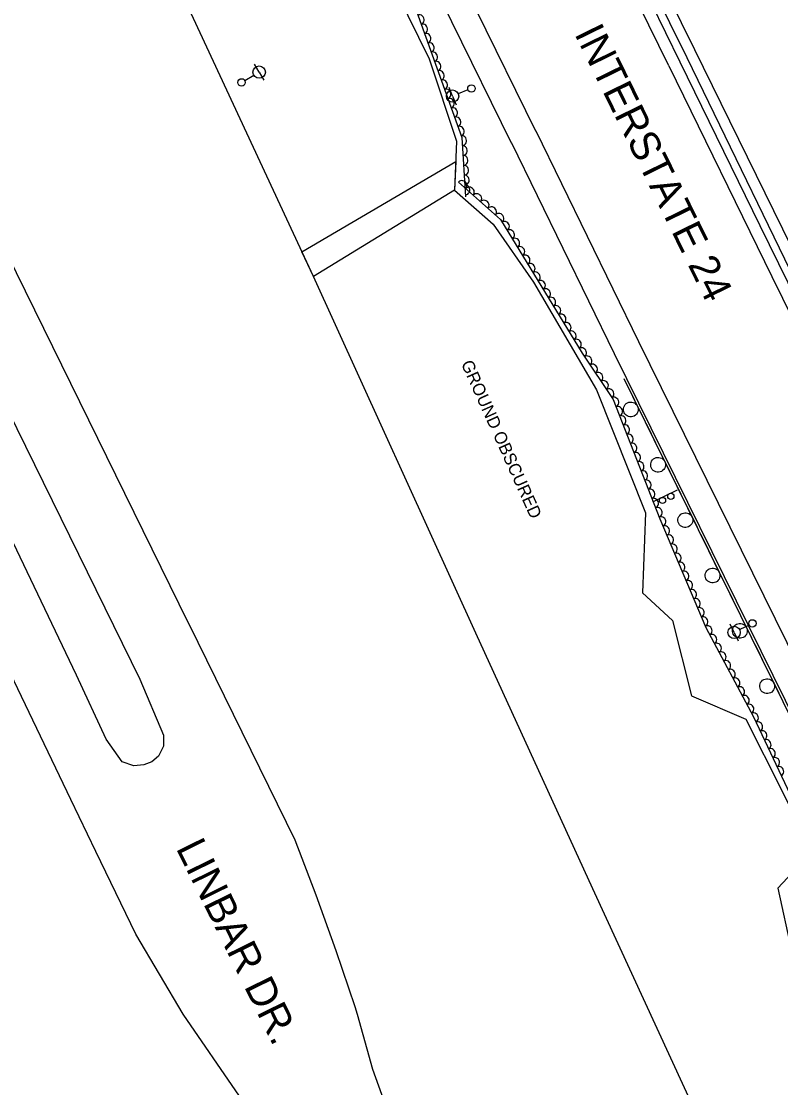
# Model space of a CAD drawing. Extents: x 1746719 to 1766531, y 631721 to 662391.
# Drawn here: x 1762510.8 to 1762818.3, y 636284.6 to 636716.8 of the extents above; entities that cross this region are included whole.
import ezdxf

# ---------------------------------------------------------------- set-up
doc = ezdxf.new("R2010")
doc.units = 0
for name, color, linetype in [('SURVEY - AERIAL SURVEY - Photo Control - Points - Elevations', 7, 'Continuous'), ('SURVEY - AERIAL SURVEY - Photo Control - Points - Locators', 7, 'Continuous'), ('SURVEY - AERIAL SURVEY - Photo Control - Points - Numbers', 7, 'Continuous'), ('SURVEY - AERIAL SURVEY - Photo Control with Text', 7, 'Continuous'), ('SURVEY - CENTERLINE - Existing Roads - Development', 7, 'Continuous'), ('SURVEY - CONTROL - Grid', 7, 'Continuous'), ('SURVEY - CONTROL - Points - Numbers', 7, 'Continuous')]:
    doc.layers.add(name, color=color, linetype=linetype)

msp = doc.modelspace()

# ---------------------------------------------------------------- linework, layer by layer
at = {"layer": 'SURVEY - AERIAL SURVEY - Photo Control - Points - Elevations'}
for points in [[(1762773.06, 636698.72), (1762724.62, 636797.23), (1762665.78, 636917.21), (1762608.96, 637033.7), (1762547.76, 637159.19), (1762483.24, 637291.54), (1762429.61, 637401.09), (1762367.13, 637528.71), (1762311.22, 637643.03), (1762248.83, 637770.86), (1762183.89, 637904.12), (1762125.15, 638021.3), (1762090.32, 638088.89)], [(1762783.5, 636705.24), (1762745.76, 636781.92), (1762702.74, 636870.15), (1762649.08, 636980.15), (1762603.69, 637072.36), (1762560.73, 637160.61), (1762512.91, 637258.85), (1762467.62, 637351.57), (1762419.77, 637449.66), (1762380.4, 637529.73), (1762340.69, 637610.68), (1762307.07, 637679.74), (1762272.3, 637751.43), (1762238.92, 637822.21), (1762204.21, 637890.89), (1762159.32, 637981.97)], [(1762719.21, 636672.25), (1762670.76, 636770.78), (1762611.89, 636890.84), (1762555.03, 637007.4), (1762493.83, 637132.9), (1762429.32, 637265.2), (1762375.72, 637374.71), (1762313.23, 637502.34), (1762254.75, 637621.92)], [(1762709.34, 636667.39), (1762660.89, 636765.94), (1762602, 636886.01), (1762545.14, 637002.58), (1762483.94, 637128.07), (1762419.44, 637260.37), (1762365.84, 637369.88), (1762303.35, 637497.51), (1762244.87, 637617.09)], [(1762369.56, 636898.24), (1762574.58, 636480.72), (1762582.23, 636465.15), (1762621.56, 636385.05), (1762630.03, 636362.79), (1762638.1, 636340.23), (1762645.78, 636317.47), (1762646.76, 636314.45), (1762653.05, 636292.18), (1762660.8, 636270.32)], [(1762557.07, 636346.83), (1762540.94, 636380.33), (1762530.76, 636401.45), (1762325.19, 636830.85)], [(1763641.05, 634952.58), (1763576.52, 635085.11), (1763508.91, 635223.28), (1763437.7, 635368.38), (1763363.42, 635520.08), (1763276.58, 635697.4), (1763200.09, 635854.25), (1763123.66, 636010.44), (1763058.89, 636142.6), (1762979.2, 636306.01), (1762911.72, 636443.92), (1762783.5, 636705.24)], [(1762556.36, 636415.05), (1762551.56, 636416.65), (1762545.17, 636425.84), (1762533.17, 636451.84), (1762423.17, 636681.84), (1762421.56, 636690.24), (1762421.56, 636695.05), (1762423.56, 636697.84), (1762428.76, 636700.24), (1762433.56, 636700.24), (1762438.76, 636694.65), (1762476.76, 636617.05), (1762558.76, 636450.24), (1762568.36, 636427.45), (1762568.36, 636423.05), (1762566.36, 636419.05), (1762563.56, 636416.65), (1762560.36, 636415.45), (1762556.36, 636415.05)], [(1762773.06, 636698.72), (1762814.67, 636613.42), (1762883.84, 636472.89), (1762954.11, 636329.07), (1763023.11, 636188.11), (1763074.26, 636083.06), (1763161.07, 635905.77), (1763211.77, 635802.95), (1763267.45, 635689.5), (1763370.88, 635477.29), (1763451.14, 635313.44)], [(1762719.13, 636672.41), (1762760.79, 636587.02), (1762829.97, 636446.47), (1762900.21, 636302.71), (1762969.19, 636161.79), (1763020.34, 636056.74), (1763107.22, 635879.31), (1763157.93, 635776.46), (1763213.56, 635663.14), (1763316.97, 635450.95), (1763397.25, 635287.05)], [(1762709.25, 636667.59), (1762750.92, 636582.18), (1762820.1, 636441.63), (1762890.33, 636297.87), (1762959.31, 636156.96), (1763010.46, 636051.91), (1763097.34, 635874.45), (1763148.06, 635771.61), (1763203.67, 635658.31), (1763307.08, 635446.12), (1763387.38, 635282.21)], [(1763135.75, 635458.81), (1763071.54, 635600.61), (1762937.1, 635866.44), (1762877.65, 635988.32), (1762874.88, 635992.15), (1762861.18, 636009.45), (1762846.27, 636025.73), (1762830.25, 636040.9), (1762813.18, 636054.88), (1762795.17, 636067.6), (1762720.15, 636117.9), (1762715.68, 636121.48), (1762700.95, 636134.6), (1762687.32, 636148.86), (1762674.91, 636164.18), (1762663.78, 636180.45), (1762654, 636197.57), (1762651.08, 636203.49), (1762639.92, 636224.16), (1762627.49, 636244.06), (1762613.86, 636263.12), (1762599.11, 636281.23), (1762576.28, 636314.43), (1762557.07, 636346.83)]]:
    msp.add_lwpolyline(points, dxfattribs=at)
at = {"layer": 'SURVEY - AERIAL SURVEY - Photo Control - Points - Locators'}
for points in [[(1762497.17, 637064.83), (1762528.12, 637009.32), (1762517.87, 636995.74), (1762516.14, 636993.28), (1762515.51, 636980.31), (1762530.55, 636960.37), (1762546.57, 636942.99), (1762556.91, 636912.32), (1762572.85, 636873.78), (1762592.05, 636832.37), (1762603.87, 636811.16), (1762624.37, 636789.49), (1762633.4, 636786.65), (1762654.39, 636745.68), (1762675.93, 636701.61), (1762687.02, 636668.3), (1762686.19, 636648.39), (1762629.1, 636613.41), (1762577.78, 636723.81), (1762533.74, 636819.19), (1762480.29, 636935.5)], [(1763204.15, 635422.43), (1763116.49, 635602.37), (1763062.75, 635714.91), (1763035.04, 635772.4), (1762997.24, 635851.96), (1762955.69, 635939.33), (1762913.53, 636023.45), (1762845.39, 636155.37), (1762784.04, 636274.28), (1762742.24, 636365.28), (1762694.9, 636468.77), (1762629.15, 636613.34), (1762624.36, 636623.35), (1762686.72, 636660.03)], [(1762686.72, 636660.03), (1762686.19, 636648.39), (1762701.82, 636634.6), (1762718.17, 636611.05), (1762743.7, 636567.48), (1762763.62, 636517.54), (1762762.41, 636485.14), (1762774.44, 636474), (1762782.25, 636443.41), (1762804.14, 636433.94), (1762818.93, 636404.82), (1762830.94, 636380.23), (1762817.12, 636365.53), (1762822.71, 636340.06), (1762848.83, 636297.5), (1762876.64, 636247.08)]]:
    msp.add_lwpolyline(points, dxfattribs=at)
at = {"layer": 'SURVEY - AERIAL SURVEY - Photo Control - Points - Numbers'}
for points in [[(1762777.65, 636700.23), (1762731.1, 636795.47), (1762662.3, 636936.22), (1762598.25, 637067), (1762540.66, 637184.6), (1762481.17, 637306.94), (1762413.68, 637445.44), (1762350.64, 637574.34), (1762291.14, 637695.72), (1762205.98, 637869.78), (1762138.69, 638007.58), (1762099.48, 638088.85)], [(1762101.32, 638090.04), (1762139.47, 638013.18), (1762181.78, 637926.27), (1762216.4, 637854.87), (1762274.24, 637736.9), (1762337.04, 637608.61), (1762400, 637479.52), (1762462.92, 637350.83), (1762538.73, 637195.19), (1762608.95, 637051.84), (1762674.55, 636917.47), (1762724.06, 636816.01), (1762780.33, 636702.09)], [(1763635.49, 634947.88), (1763550.57, 635121.13), (1763412.96, 635402), (1763296.92, 635639.14), (1763179.78, 635878.6), (1763016.73, 636211.43), (1762900.31, 636449.87), (1762810.07, 636633.97), (1762777.65, 636700.23)], [(1762780.33, 636702.09), (1762833.11, 636593.25), (1762910.17, 636436.51), (1763005.6, 636241.46), (1763118.37, 636010.26), (1763219.08, 635804.06), (1763329.74, 635578.22), (1763441.15, 635350.94), (1763538.42, 635152.66), (1763637.77, 634949.46)], [(1762754.81, 636572), (1762819.2, 636441.19), (1762889.43, 636297.43), (1762958.41, 636156.52), (1763009.56, 636051.47), (1763096.45, 635874.01), (1763147.16, 635771.16), (1763186.04, 635691.97)], [(1762754.81, 636572), (1762756.89, 636567.78)], [(1762758.3, 636564.91), (1762762.36, 636556.65)], [(1762763.78, 636553.78), (1762765.85, 636549.57)], [(1762765.85, 636549.57), (1762767.93, 636545.35)], [(1762769.34, 636542.48), (1762773.41, 636534.22)], [(1762774.82, 636531.35), (1762776.9, 636527.14)], [(1762776.9, 636527.14), (1762778.97, 636522.92)], [(1762780.38, 636520.05), (1762784.45, 636511.79)], [(1762785.86, 636508.92), (1762787.94, 636504.71)], [(1762787.94, 636504.71), (1762790.01, 636500.49)], [(1762791.42, 636497.62), (1762795.49, 636489.36)], [(1762796.9, 636486.49), (1762798.98, 636482.28)], [(1762798.98, 636482.28), (1762801.05, 636478.06)], [(1762802.47, 636475.19), (1762806.53, 636466.93)], [(1762807.94, 636464.06), (1762810.02, 636459.85)], [(1762810.02, 636459.85), (1762812.09, 636455.63)], [(1762813.51, 636452.76), (1762817.57, 636444.5)]]:
    msp.add_lwpolyline(points, dxfattribs=at)
for centre in [(1762757.62, 636559.5), (1762768.66, 636537.07), (1762779.7, 636514.64), (1762790.74, 636492.21), (1762801.79, 636469.78), (1762812.83, 636447.35)]:
    msp.add_arc(centre, 3, 139.4761, 139.4621, dxfattribs=at)
at = {"layer": 'SURVEY - AERIAL SURVEY - Photo Control with Text'}
for points in [[(1762343.29, 637381.3), (1762378.31, 637308.67), (1762402.8, 637267.98), (1762439.16, 637196), (1762472.65, 637120.38), (1762509.6, 637045.79), (1762531.2, 637005.81), (1762519.79, 636993.53), (1762518.61, 636981.54), (1762547.16, 636946.64), (1762556.36, 636921.7), (1762578.74, 636868.77), (1762606.57, 636810.33), (1762625.84, 636791.03), (1762635.96, 636787.79), (1762670.78, 636720.91), (1762689.11, 636669.78), (1762690.71, 636645.62)], [(1762687.81, 636651.66), (1762704.83, 636636.5), (1762737.9, 636582.29), (1762750.43, 636563.52), (1762769.4, 636515.18), (1762787.94, 636471.17), (1762807.26, 636434.86), (1762833.45, 636379.41), (1762821.62, 636361.1), (1762827.53, 636338.34), (1762856.61, 636295.22), (1762881.67, 636249.02)]]:
    msp.add_lwpolyline(points, dxfattribs=at)
for centre, major_axis in [((1762672.01, 636717.47), (0.67, -1.88)), ((1762673.36, 636713.7), (0.67, -1.88)), ((1762674.71, 636709.94), (0.67, -1.88)), ((1762676.06, 636706.17), (0.67, -1.88)), ((1762677.41, 636702.4), (0.67, -1.88)), ((1762678.76, 636698.64), (0.67, -1.88)), ((1762680.11, 636694.87), (0.67, -1.88)), ((1762681.46, 636691.11), (0.67, -1.88)), ((1762682.81, 636687.34), (0.67, -1.88)), ((1762684.16, 636683.58), (0.67, -1.88)), ((1762685.51, 636679.81), (0.67, -1.88)), ((1762686.86, 636676.05), (0.67, -1.88)), ((1762688.21, 636672.28), (0.67, -1.88)), ((1762689.2, 636668.44), (0.13, -2)), ((1762689.46, 636664.45), (0.13, -2)), ((1762689.73, 636660.46), (0.13, -2)), ((1762689.99, 636656.47), (0.13, -2)), ((1762689.3, 636650.33), (1.49, -1.33)), ((1762690.25, 636652.47), (0.13, -2)), ((1762690.52, 636648.48), (0.13, -2)), ((1762692.29, 636647.67), (1.49, -1.33)), ((1762695.27, 636645.01), (1.49, -1.33)), ((1762698.26, 636642.35), (1.49, -1.33)), ((1762701.25, 636639.69), (1.49, -1.33)), ((1762704.24, 636637.03), (1.49, -1.33)), ((1762706.5, 636633.77), (1.04, -1.71)), ((1762708.58, 636630.35), (1.04, -1.71)), ((1762710.66, 636626.94), (1.04, -1.71)), ((1762712.75, 636623.52), (1.04, -1.71)), ((1762714.83, 636620.11), (1.04, -1.71)), ((1762716.91, 636616.69), (1.04, -1.71)), ((1762719, 636613.28), (1.04, -1.71)), ((1762721.08, 636609.86), (1.04, -1.71)), ((1762723.16, 636606.45), (1.04, -1.71)), ((1762725.24, 636603.03), (1.04, -1.71)), ((1762727.33, 636599.62), (1.04, -1.71)), ((1762729.41, 636596.2), (1.04, -1.71)), ((1762731.49, 636592.79), (1.04, -1.71)), ((1762733.57, 636589.37), (1.04, -1.71)), ((1762735.66, 636585.96), (1.04, -1.71)), ((1762737.74, 636582.54), (1.04, -1.71)), ((1762739.95, 636579.21), (1.11, -1.66)), ((1762742.17, 636575.88), (1.11, -1.66)), ((1762744.4, 636572.56), (1.11, -1.66)), ((1762746.62, 636569.23), (1.11, -1.66)), ((1762748.84, 636565.9), (1.11, -1.66)), ((1762750.85, 636562.47), (0.73, -1.86)), ((1762752.31, 636558.74), (0.73, -1.86)), ((1762753.77, 636555.02), (0.73, -1.86)), ((1762755.23, 636551.29), (0.73, -1.86)), ((1762756.69, 636547.57), (0.73, -1.86)), ((1762758.15, 636543.85), (0.73, -1.86)), ((1762759.61, 636540.12), (0.73, -1.86)), ((1762761.07, 636536.4), (0.73, -1.86)), ((1762762.53, 636532.68), (0.73, -1.86)), ((1762763.99, 636528.95), (0.73, -1.86)), ((1762765.46, 636525.23), (0.73, -1.86)), ((1762766.92, 636521.51), (0.73, -1.86)), ((1762768.38, 636517.78), (0.73, -1.86)), ((1762769.87, 636514.07), (0.78, -1.84)), ((1762771.42, 636510.38), (0.78, -1.84)), ((1762772.97, 636506.7), (0.78, -1.84)), ((1762774.53, 636503.01), (0.78, -1.84)), ((1762776.08, 636499.32), (0.78, -1.84)), ((1762777.63, 636495.64), (0.78, -1.84)), ((1762779.18, 636491.95), (0.78, -1.84)), ((1762780.74, 636488.27), (0.78, -1.84)), ((1762782.29, 636484.58), (0.78, -1.84)), ((1762783.84, 636480.89), (0.78, -1.84)), ((1762785.4, 636477.21), (0.78, -1.84)), ((1762786.95, 636473.52), (0.78, -1.84)), ((1762788.62, 636469.89), (0.94, -1.77)), ((1762790.5, 636466.36), (0.94, -1.77)), ((1762792.38, 636462.83), (0.94, -1.77)), ((1762794.26, 636459.3), (0.94, -1.77)), ((1762796.14, 636455.77), (0.94, -1.77)), ((1762798.01, 636452.23), (0.94, -1.77)), ((1762799.89, 636448.7), (0.94, -1.77)), ((1762801.77, 636445.17), (0.94, -1.77)), ((1762803.65, 636441.64), (0.94, -1.77)), ((1762805.53, 636438.11), (0.94, -1.77)), ((1762807.39, 636434.57), (0.85, -1.81)), ((1762809.1, 636430.95), (0.85, -1.81)), ((1762810.81, 636427.34), (0.85, -1.81)), ((1762812.52, 636423.72), (0.85, -1.81)), ((1762814.23, 636420.1), (0.85, -1.81)), ((1762815.94, 636416.49), (0.85, -1.81)), ((1762817.64, 636412.87), (0.85, -1.81))]:
    msp.add_ellipse(centre, major_axis=major_axis, ratio=0.940188, start_param=0, end_param=3.141593, dxfattribs=at)
at = {"layer": 'SURVEY - CENTERLINE - Existing Roads - Development'}
for p, q in [((1762607.09, 636696.21), (1762605.2, 636699.45)), ((1762607.09, 636696.21), (1762608.98, 636692.97)), ((1762601.26, 636692.81), (1762604.93, 636694.95)), ((1762685.41, 636686.5), (1762684, 636689.97)), ((1762685.41, 636686.5), (1762686.82, 636683.02)), ((1762691.66, 636689.04), (1762687.72, 636687.44)), ((1762799.47, 636469.15), (1762797.81, 636472.51)), ((1762805.52, 636472.14), (1762801.71, 636470.26)), ((1762799.47, 636469.15), (1762801.13, 636465.79))]:
    msp.add_line(p, q, dxfattribs=at)
for centre, radius in [((1762607.09, 636696.21), 2.5), ((1762599.96, 636692.05), 1.5), ((1762693.05, 636689.6), 1.5), ((1762685.41, 636686.5), 2.5), ((1762799.47, 636469.15), 2.5), ((1762806.87, 636472.8), 1.5)]:
    msp.add_circle(centre, radius, dxfattribs=at)
at = {"layer": 'SURVEY - CONTROL - Grid'}
msp.add_line((1762766.48, 636522.03), (1762776.54, 636526.96), dxfattribs=at)
for centre in [(1762770.45, 636522.61), (1762773.82, 636524.26)]:
    msp.add_circle(centre, 1.25, dxfattribs=at)

# ---------------------------------------------------------------- texts
at = {"layer": 'SURVEY - AERIAL SURVEY - Photo Control - Points - Locators'}
msp.add_text('GROUND OBSCURED', height=5, rotation=294.1985, dxfattribs=at).set_placement((1762688.75, 636578.11))
at = {"layer": 'SURVEY - CONTROL - Points - Numbers'}
for s, rotation, p in [('INTERSTATE 24', 296.1451, (1762734.6, 636711.87)), ('LINBAR DR.', 296.222, (1762573.23, 636381.76))]:
    msp.add_text(s, height=12, rotation=rotation, dxfattribs=at).set_placement(p)

doc.saveas('drawing.dxf')
